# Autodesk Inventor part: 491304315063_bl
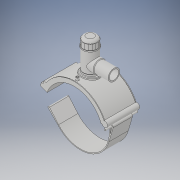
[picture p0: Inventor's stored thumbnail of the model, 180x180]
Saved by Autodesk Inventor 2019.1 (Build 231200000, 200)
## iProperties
Created: 2017-07
Part Number: 491304315063_bl
Material: Generic
Description: PLASSON TAPPING TEE SADDLE 315mm x 63mm
Document SubType Name: Modeling
Designer: KIM
Mass: 1712.7 g
Surface Area: 2671.49 cm^2
Volume: 1712.7 cm^3
Density: 1 g/cm^3
Appearance: Default
Author: KIM
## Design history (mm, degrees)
derived "491304.ipt"
feature "Solid1::491304.ipt" dims "ScaleForDerivedMember" = 10
feature "Solid2::491304.ipt" dims "ScaleForDerivedMember" = 10
feature "Solid4::491304.ipt" dims "ScaleForDerivedMember" = 10
feature "Solid5::491304.ipt" dims "ScaleForDerivedMember" = 10
tag "TaggingFeature1"
body "Solid1"
body "Solid2"
other parameters: "d0" = 315 [user parameter], "d1" = 101.118 [user parameter], "d2" = 292.8 [user parameter], "d3" = 78.75 [user parameter], "d4" = 176 [user parameter], "d5" = 0 [user parameter], "d6" = 0.1 [user parameter], "d8" = 0 [user parameter], "d40" = 189 [user parameter], "d41" = 97.65 [user parameter], "d43" = 0 [user parameter], "d45" = 0 [user parameter], "d47" = 156.159 [user parameter], "d78" = 192.5 [user parameter], "d79" = 15 [user parameter], "d80" = 70.4 [user parameter], "d82" = 5 deg [user parameter], "d84" = 4 [user parameter], "d85" = 14 [user parameter], "d86" = 0 [user parameter], "d87" = 3 [user parameter], "d88" = 0 [user parameter], "d97" = 3.52 [user parameter], "d98" = 0 [user parameter], "d102" = 3.15 [user parameter], "d120" = 140 deg [user parameter], "d123" = 606.708 [user parameter], "d126" = 0 [user parameter], "d153" = 176 [user parameter], "d154" = 0 [user parameter], "d159" = -42.7764 [user parameter], "d162" = 105.6 [user parameter], "d163" = 0 [user parameter], "d164" = 157.5 [user parameter], "d169" = 4.0905 [user parameter], "d172" = 0 [user parameter], "d173" = 1 [user parameter], "d175" = 157.5 [user parameter], "d176" = 20 deg [user parameter], "d177" = 22.05 [user parameter], "d180" = 0 [user parameter], "d184" = 17.64 [user parameter], "d187" = 173.25 [user parameter], "d188" = 15 [user parameter], "d189" = 22.05 [user parameter], "d190" = 0 [user parameter], "d191" = 236.25 [user parameter], "d195" = 90 deg [user parameter], "d197" = 0 [user parameter], "d199" = 0 [user parameter], "d200" = 22.05 [user parameter], "d202" = 0 [user parameter], "d203" = 195 [user parameter], "d206" = 75.6 [user parameter], "d207" = 146.25 [user parameter], "d208" = 152.1 [user parameter], "d209" = 181.35 [user parameter], "d210" = 76.86 [user parameter], "d212" = 72.45 [user parameter], "d213" = 39.15 [user parameter], "d216" = 0 [user parameter], "d217" = 31.5 [user parameter], "d218" = 15.75 [user parameter], "d219" = 3.15 [user parameter], "d222" = 315 [user parameter], "d224" = 0 [user parameter], "d259" = 50.4 [user parameter], "d260" = 63 [user parameter], "d263" = 183 [user parameter], "d265" = 0 [user parameter], "d267" = 13.00006 [user parameter], "d268" = 2.60001 [user parameter], "d269" = 2.60001 [user parameter], "d271" = 2.60001 [user parameter], "d273" = 0 [user parameter], "d274" = 23.56194 [user parameter], "d275" = 252 [user parameter], "d277" = 126 [user parameter], "d278" = 504 [user parameter], "d280" = 0 [user parameter], "d281" = 315 [user parameter], "d283" = 0 [user parameter], "d285" = 0 [user parameter], "d290" = 31.5 [user parameter], "d293" = 173.25 [user parameter], "d294" = 162.225 [user parameter], "d296" = 47.25 [user parameter], "d299" = 75 [user parameter], "d300" = 3 [user parameter], "d301" = 5 [user parameter], "d303" = 81.9 [user parameter], "d304" = 69.3 [user parameter], "d305" = 45 deg [user parameter], "d306" = 50.4 [user parameter], "d307" = 196.875 [user parameter], "d308" = 189 [user parameter], "d309" = 1575 [user parameter], "d310" = 1 [user parameter], "d314" = 945 [user parameter], "d" = 315 [user parameter], "B" = 183 [user parameter], "L" = 176 [user parameter], "d_t" = 6 [user parameter], "H2" = 195 [user parameter], "H1" = 75 [user parameter], "d_1" = 63 [user parameter]
